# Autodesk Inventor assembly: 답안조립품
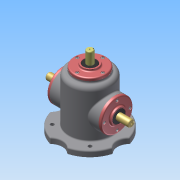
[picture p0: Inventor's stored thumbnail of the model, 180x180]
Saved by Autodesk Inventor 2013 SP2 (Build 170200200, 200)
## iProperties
Created: 2026-07
Part Number: 답안조립품
Document SubType Name: Assembly
Designer: aa
Author: aa
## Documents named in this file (19)
- C:\Users\aa\Desktop\760703V1001\답안조립품.iam
- C:\Users\aa\Desktop\760703V1001\본체.ipt
- C:\Users\aa\Desktop\760703V1001\깊은 홈 볼 베어링 6203.ipt
- C:\Users\aa\Desktop\760703V1001\커버.ipt
- C:\Users\aa\Desktop\760703V1001\오일 실 17 32 8.ipt
- C:\Users\aa\Desktop\760703V1001\6각 구멍붙이 볼트 M4x10.ipt
- C:\Users\aa\Desktop\760703V1001\깊은 홈 볼 베어링 6203_MIR.ipt
- C:\Users\aa\Desktop\760703V1001\커버_MIR.ipt
- C:\Users\aa\Desktop\760703V1001\오일 실 17 32 8_MIR.ipt
- C:\Users\aa\Desktop\760703V1001\6각 구멍붙이 볼트 M4x10_MIR.ipt
- C:\Users\aa\Desktop\760703V1001\메인 축.ipt
- C:\Users\aa\Desktop\760703V1001\평행 키 5x5x14.ipt
- C:\Users\aa\Desktop\760703V1001\메인 베벨기어.ipt
- C:\Users\aa\Desktop\760703V1001\메인 축_MIR.ipt
- C:\Users\aa\Desktop\760703V1001\평행 키 5x5x14_MIR.ipt
- C:\Users\aa\Desktop\760703V1001\메인 베벨기어_MIR.ipt
- C:\Users\aa\Desktop\760703V1001\서브 축.ipt
- C:\Users\aa\Desktop\760703V1001\평행 키 4x4x14.ipt
- C:\Users\aa\Desktop\760703V1001\서브 베벨기어.ipt
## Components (12 placed, 2 different names)
1. 6각 구멍붙이 볼트 M4x10:1
2. 6각 구멍붙이 볼트 M4x10:2
3. 6각 구멍붙이 볼트 M4x10:3
4. 6각 구멍붙이 볼트 M4x10:4
5. 6각 구멍붙이 볼트 M4x10_MIR:1
6. 6각 구멍붙이 볼트 M4x10_MIR:2
7. 6각 구멍붙이 볼트 M4x10_MIR:3
8. 6각 구멍붙이 볼트 M4x10_MIR:4
9. 6각 구멍붙이 볼트 M4x10:5
10. 6각 구멍붙이 볼트 M4x10:6
11. 6각 구멍붙이 볼트 M4x10:7
12. 6각 구멍붙이 볼트 M4x10:8
